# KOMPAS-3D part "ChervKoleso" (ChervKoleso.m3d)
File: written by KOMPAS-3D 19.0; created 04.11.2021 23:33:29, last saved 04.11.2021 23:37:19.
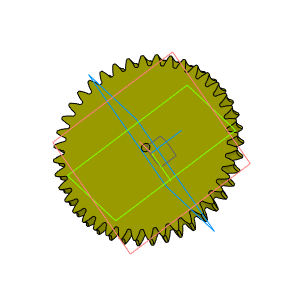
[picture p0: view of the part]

Document properties: Полное имя файла: D:\3D_print\3D проекты Компас 3D\Редуктор (Снова)\ChervKoleso.m3d

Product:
- Part/product: ChervKoleso
    Материал: АБС 0603Т ТУ 2214-019-002 03521-96 (density 0 kg/m3)
    Комментарий: Модуль генерации 3D-моделей программы "Валы и механические передачи 2D"
  - Body: Тело 1
      Масса: 0.133846

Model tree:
1. Внеш. контур, ступень 1: Червячное колесо (тип ZA, правое) Z=40, L=6, Средняя плоскость
     Расстояние = 3
2. Внеш. контур, ступень 1: Червячное колесо (тип ZA, правое) Z=40, L=6, Плоскость межосевого расстояния
     Расстояние = 37.5
3. Внеш. контур, ступень 1: Червячное колесо (тип ZA, правое) Z=40, L=6, Ось исходного червяка
4. Эскиз:1
5. Внеш. контур, ступень 1: Червячное колесо (тип ZA, правое) Z=40, L=6
     Расстояние 2 = 6; Смещение 2 = 6
6. Ось операции:1
7. Эскиз:2
8. Внеш. контур, ступень 1: Червячное колесо (тип ZA, правое) Z=40, L=6: выемка поверхности вершин зубьев
     Угол 1 = 360
9. Внеш. контур, ступень 1: Червячное колесо (тип ZA, правое) Z=40, L=6, ЛСК зубчатого венца  (with: Плоскость XY, Плоскость ZX, Плоскость ZY, Ось X, Ось Y, Ось Z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)
     Ось X. X = 1; Ось Y. Y = 1; Ось Z. Z = 1
10. Точка:1
11. Точка:2
     X = 6; Координата X = 6
12. Осевая линия:1
13. Эскиз:3
14. Элемент выдавливания:2  (labels: АБС 0603Т ТУ 2214-019-002 03521-96)
     Расстояние 2 = 6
